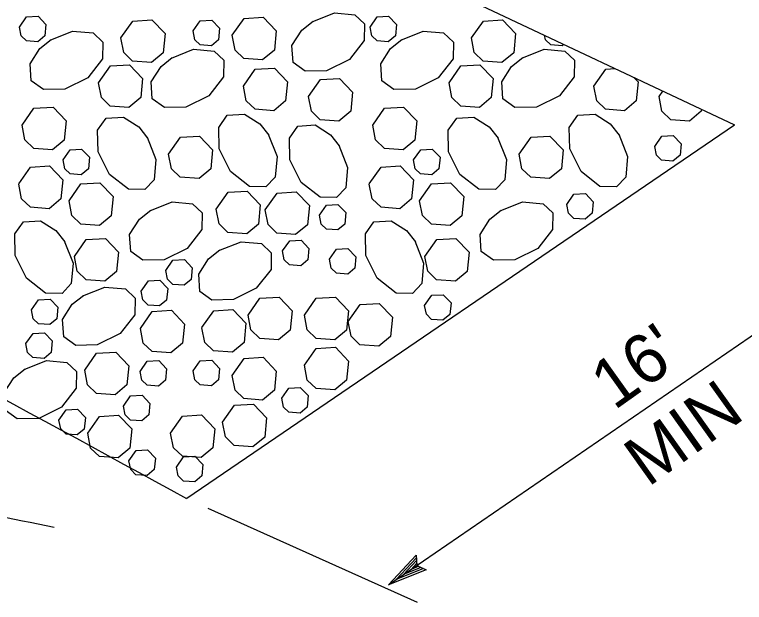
# Model space of a CAD drawing. Extents: x 6709491 to 6710959, y 1869789 to 1870763.
# Drawn here: x 6710751.9 to 6710858.5, y 1870263.6 to 1870349.5 of the extents above; entities that cross this region are included whole.
import ezdxf

# ---------------------------------------------------------------- set-up
doc = ezdxf.new("R2010")
doc.units = 0
for name, color, linetype in [('56 Stg 3 Anno', 7, 'Continuous'), ('57 Undefined', 7, 'Continuous'), ('60 Nongeo Data', 7, 'Continuous')]:
    doc.layers.add(name, color=color, linetype=linetype)

msp = doc.modelspace()

# ---------------------------------------------------------------- linework, layer by layer
at = {"layer": '56 Stg 3 Anno'}
for p, q in [((6710806.49, 1870266.16), (6710885.13, 1870320.15)), ((6710810.73, 1870263.58), (6710780.13, 1870277.31)), ((6710806.49, 1870266.16), (6710810.52, 1870270.48)), ((6710807.59, 1870266.92), (6710810.53, 1870270.06)), ((6710808.68, 1870267.66), (6710810.58, 1870269.69)), ((6710810.52, 1870270.48), (6710810.52, 1870270.48)), ((6710810.52, 1870270.48), (6710810.61, 1870268.99)), ((6710811.22, 1870268.68), (6710808.68, 1870267.66)), ((6710809.77, 1870268.41), (6710810.59, 1870269.28)), ((6710810.9, 1870268.86), (6710809.77, 1870268.41)), ((6710810.61, 1870268.99), (6710811.97, 1870268.36)), ((6710811.97, 1870268.36), (6710806.49, 1870266.16)), ((6710811.6, 1870268.53), (6710807.59, 1870266.91)), ((6710811.97, 1870268.36), (6710811.97, 1870268.36)), ((6710806.49, 1870266.16), (6710806.49, 1870266.16))]:
    msp.add_line(p, q, dxfattribs=at)
at = {"layer": '60 Nongeo Data'}
for p, q in [((6710717.37, 1870399.17), (6710856.99, 1870333.37)), ((6710777.01, 1870278.8), (6710857.03, 1870333.34))]:
    msp.add_line(p, q, dxfattribs=at)
for points in [[(6710795.32, 1870348.4), (6710798.58, 1870349.69), (6710801.57, 1870349.44), (6710802.99, 1870348.09), (6710802.94, 1870345.66), (6710800.79, 1870342.9), (6710797.45, 1870341.24), (6710794.31, 1870341.18), (6710792.55, 1870342.44), (6710792.38, 1870344.94), (6710793.81, 1870347.18), (6710795.46, 1870348.49)], [(6710752.59, 1870347.64), (6710753.63, 1870349.12), (6710755.3, 1870349.22), (6710756.45, 1870348.02), (6710756.29, 1870346.33), (6710755.26, 1870345.48), (6710753.61, 1870345.6), (6710752.84, 1870346.35), (6710752.59, 1870347.64)], [(6710767.4, 1870346.05), (6710769.14, 1870348.52), (6710771.91, 1870348.68), (6710773.85, 1870346.68), (6710773.57, 1870343.88), (6710771.85, 1870342.45), (6710769.11, 1870342.65), (6710767.82, 1870343.9), (6710767.4, 1870346.05)], [(6710777.95, 1870347.07), (6710779, 1870348.55), (6710780.66, 1870348.65), (6710781.82, 1870347.45), (6710781.65, 1870345.76), (6710780.62, 1870344.91), (6710778.98, 1870345.03), (6710778.2, 1870345.78), (6710777.95, 1870347.07)], [(6710783.65, 1870346.43), (6710785.39, 1870348.9), (6710788.17, 1870349.06), (6710790.1, 1870347.06), (6710789.82, 1870344.25), (6710788.1, 1870342.83), (6710785.36, 1870343.02), (6710784.07, 1870344.28), (6710783.65, 1870346.43)], [(6710803.78, 1870347.64), (6710804.82, 1870349.12), (6710806.49, 1870349.22), (6710807.65, 1870348.02), (6710807.48, 1870346.33), (6710806.45, 1870345.48), (6710804.81, 1870345.6), (6710804.03, 1870346.35), (6710803.78, 1870347.64)], [(6710818.59, 1870346.05), (6710820.33, 1870348.52), (6710823.11, 1870348.68), (6710825.04, 1870346.68), (6710824.76, 1870343.88), (6710823.04, 1870342.45), (6710820.3, 1870342.65), (6710819.01, 1870343.9), (6710818.59, 1870346.05)], [(6710757.09, 1870345.73), (6710760.35, 1870347.02), (6710763.34, 1870346.77), (6710764.76, 1870345.42), (6710764.71, 1870342.99), (6710762.56, 1870340.23), (6710759.22, 1870338.57), (6710756.08, 1870338.51), (6710754.32, 1870339.77), (6710754.15, 1870342.27), (6710755.58, 1870344.51), (6710757.23, 1870345.82)], [(6710808.29, 1870345.73), (6710811.54, 1870347.02), (6710814.53, 1870346.77), (6710815.95, 1870345.42), (6710815.9, 1870342.99), (6710813.75, 1870340.23), (6710810.42, 1870338.57), (6710807.28, 1870338.51), (6710805.51, 1870339.77), (6710805.34, 1870342.27), (6710806.78, 1870344.51), (6710808.42, 1870345.82)], [(6710832.07, 1870345.11), (6710831.82, 1870344.91), (6710830.17, 1870345.03), (6710829.4, 1870345.78), (6710829.27, 1870346.43)], [(6710774.77, 1870343.1), (6710778.02, 1870344.39), (6710781.01, 1870344.13), (6710782.43, 1870342.78), (6710782.39, 1870340.36), (6710780.23, 1870337.6), (6710776.9, 1870335.94), (6710773.76, 1870335.88), (6710771.99, 1870337.14), (6710771.83, 1870339.64), (6710773.26, 1870341.88), (6710774.9, 1870343.19)], [(6710825.96, 1870343.1), (6710829.22, 1870344.39), (6710832.21, 1870344.13), (6710833.63, 1870342.78), (6710833.58, 1870340.36), (6710831.43, 1870337.6), (6710828.09, 1870335.94), (6710824.95, 1870335.88), (6710823.19, 1870337.14), (6710823.02, 1870339.64), (6710824.45, 1870341.88), (6710826.1, 1870343.19)], [(6710764.13, 1870339.5), (6710765.87, 1870341.98), (6710768.64, 1870342.14), (6710770.57, 1870340.14), (6710770.29, 1870337.33), (6710768.58, 1870335.9), (6710765.84, 1870336.1), (6710764.55, 1870337.35), (6710764.13, 1870339.5)], [(6710815.32, 1870339.5), (6710817.06, 1870341.98), (6710819.84, 1870342.14), (6710821.77, 1870340.14), (6710821.49, 1870337.33), (6710819.77, 1870335.9), (6710817.03, 1870336.1), (6710815.74, 1870337.35), (6710815.32, 1870339.5)], [(6710785.29, 1870339.02), (6710787.03, 1870341.49), (6710789.81, 1870341.65), (6710791.74, 1870339.65), (6710791.46, 1870336.85), (6710789.74, 1870335.42), (6710787, 1870335.62), (6710785.71, 1870336.87), (6710785.29, 1870339.02)], [(6710836.48, 1870339.02), (6710838.22, 1870341.49), (6710839.58, 1870341.57)], [(6710794.8, 1870337.5), (6710796.54, 1870339.98), (6710799.31, 1870340.14), (6710801.24, 1870338.14), (6710800.97, 1870335.33), (6710799.25, 1870333.9), (6710796.51, 1870334.1), (6710795.22, 1870335.35), (6710794.8, 1870337.5)], [(6710842.32, 1870340.28), (6710842.93, 1870339.65), (6710842.65, 1870336.85), (6710840.93, 1870335.42), (6710838.19, 1870335.62), (6710836.9, 1870336.87), (6710836.48, 1870339.02)], [(6710845.99, 1870337.5), (6710846.54, 1870338.29)], [(6710852.19, 1870335.63), (6710852.16, 1870335.33), (6710850.44, 1870333.9), (6710847.7, 1870334.1), (6710846.41, 1870335.35), (6710845.99, 1870337.5)], [(6710752.97, 1870333.3), (6710754.71, 1870335.77), (6710757.49, 1870335.93), (6710759.42, 1870333.93), (6710759.14, 1870331.12), (6710757.43, 1870329.7), (6710754.68, 1870329.89), (6710753.39, 1870331.15), (6710752.97, 1870333.3)], [(6710804.17, 1870333.3), (6710805.91, 1870335.77), (6710808.68, 1870335.93), (6710810.61, 1870333.93), (6710810.33, 1870331.12), (6710808.62, 1870329.7), (6710805.88, 1870329.89), (6710804.59, 1870331.15), (6710804.17, 1870333.3)], [(6710788.91, 1870331.97), (6710790.2, 1870328.72), (6710789.94, 1870325.73), (6710788.59, 1870324.31), (6710786.16, 1870324.35), (6710783.41, 1870326.51), (6710781.74, 1870329.84), (6710781.69, 1870332.98), (6710782.94, 1870334.75), (6710785.44, 1870334.92), (6710787.68, 1870333.48), (6710788.99, 1870331.84)], [(6710840.1, 1870331.97), (6710841.39, 1870328.72), (6710841.13, 1870325.73), (6710839.78, 1870324.31), (6710837.36, 1870324.35), (6710834.6, 1870326.51), (6710832.94, 1870329.84), (6710832.88, 1870332.98), (6710834.14, 1870334.75), (6710836.64, 1870334.92), (6710838.87, 1870333.48), (6710840.18, 1870331.84)], [(6710771.23, 1870331.55), (6710772.52, 1870328.3), (6710772.26, 1870325.31), (6710770.91, 1870323.89), (6710768.49, 1870323.93), (6710765.73, 1870326.09), (6710764.07, 1870329.42), (6710764.01, 1870332.56), (6710765.27, 1870334.33), (6710767.77, 1870334.49), (6710770, 1870333.06), (6710771.31, 1870331.42)], [(6710822.42, 1870331.55), (6710823.71, 1870328.3), (6710823.46, 1870325.31), (6710822.11, 1870323.89), (6710819.68, 1870323.93), (6710816.92, 1870326.09), (6710815.26, 1870329.42), (6710815.2, 1870332.56), (6710816.46, 1870334.33), (6710818.96, 1870334.49), (6710821.2, 1870333.06), (6710822.51, 1870331.42)], [(6710799.22, 1870330.39), (6710800.51, 1870327.14), (6710800.25, 1870324.15), (6710798.9, 1870322.73), (6710796.48, 1870322.77), (6710793.72, 1870324.93), (6710792.05, 1870328.26), (6710792, 1870331.4), (6710793.26, 1870333.17), (6710795.76, 1870333.34), (6710797.99, 1870331.9), (6710799.3, 1870330.26)], [(6710774.36, 1870329.09), (6710776.09, 1870331.56), (6710778.87, 1870331.72), (6710780.8, 1870329.72), (6710780.52, 1870326.92), (6710778.81, 1870325.49), (6710776.07, 1870325.69), (6710774.78, 1870326.94), (6710774.36, 1870329.09)], [(6710825.55, 1870329.09), (6710827.29, 1870331.56), (6710830.06, 1870331.72), (6710832, 1870329.72), (6710831.72, 1870326.92), (6710830, 1870325.49), (6710827.26, 1870325.69), (6710825.97, 1870326.94), (6710825.55, 1870329.09)], [(6710845.35, 1870330.21), (6710846.39, 1870331.7), (6710848.06, 1870331.79), (6710849.22, 1870330.59), (6710849.05, 1870328.91), (6710848.02, 1870328.05), (6710846.37, 1870328.17), (6710845.6, 1870328.92), (6710845.35, 1870330.21)], [(6710758.95, 1870328.23), (6710759.99, 1870329.71), (6710761.66, 1870329.81), (6710762.82, 1870328.61), (6710762.65, 1870326.92), (6710761.62, 1870326.07), (6710759.97, 1870326.19), (6710759.2, 1870326.94), (6710758.95, 1870328.23)], [(6710810.14, 1870328.23), (6710811.19, 1870329.71), (6710812.85, 1870329.81), (6710814.01, 1870328.61), (6710813.84, 1870326.92), (6710812.81, 1870326.07), (6710811.17, 1870326.19), (6710810.39, 1870326.94), (6710810.14, 1870328.23)], [(6710752.49, 1870324.71), (6710754.22, 1870327.18), (6710757, 1870327.34), (6710758.93, 1870325.34), (6710758.65, 1870322.53), (6710756.94, 1870321.1), (6710754.19, 1870321.3), (6710752.91, 1870322.55), (6710752.49, 1870324.7)], [(6710803.68, 1870324.71), (6710805.42, 1870327.18), (6710808.2, 1870327.34), (6710810.13, 1870325.34), (6710809.85, 1870322.53), (6710808.13, 1870321.1), (6710805.39, 1870321.3), (6710804.1, 1870322.55), (6710803.68, 1870324.7)], [(6710759.83, 1870322.25), (6710761.57, 1870324.72), (6710764.35, 1870324.88), (6710766.28, 1870322.88), (6710766, 1870320.07), (6710764.29, 1870318.65), (6710761.54, 1870318.85), (6710760.26, 1870320.1), (6710759.84, 1870322.25)], [(6710811.03, 1870322.25), (6710812.77, 1870324.72), (6710815.54, 1870324.88), (6710817.48, 1870322.88), (6710817.2, 1870320.07), (6710815.48, 1870318.65), (6710812.74, 1870318.85), (6710811.45, 1870320.1), (6710811.03, 1870322.25)], [(6710781.32, 1870321.02), (6710783.06, 1870323.5), (6710785.83, 1870323.66), (6710787.76, 1870321.65), (6710787.48, 1870318.85), (6710785.77, 1870317.42), (6710783.03, 1870317.62), (6710781.74, 1870318.87), (6710781.32, 1870321.02)], [(6710788.47, 1870320.92), (6710790.21, 1870323.39), (6710792.99, 1870323.55), (6710794.92, 1870321.55), (6710794.64, 1870318.74), (6710792.92, 1870317.32), (6710790.18, 1870317.52), (6710788.89, 1870318.77), (6710788.47, 1870320.92)], [(6710832.52, 1870321.73), (6710833.56, 1870323.22), (6710835.23, 1870323.31), (6710836.39, 1870322.11), (6710836.22, 1870320.43), (6710835.19, 1870319.57), (6710833.54, 1870319.69), (6710832.77, 1870320.44), (6710832.52, 1870321.73)], [(6710771.61, 1870320.8), (6710774.87, 1870322.09), (6710777.86, 1870321.83), (6710779.28, 1870320.48), (6710779.23, 1870318.05), (6710777.08, 1870315.3), (6710773.74, 1870313.63), (6710770.6, 1870313.57), (6710768.84, 1870314.83), (6710768.67, 1870317.33), (6710770.1, 1870319.57), (6710771.75, 1870320.88)], [(6710822.81, 1870320.8), (6710826.06, 1870322.09), (6710829.05, 1870321.83), (6710830.47, 1870320.48), (6710830.43, 1870318.05), (6710828.27, 1870315.3), (6710824.94, 1870313.63), (6710821.8, 1870313.57), (6710820.03, 1870314.83), (6710819.86, 1870317.33), (6710821.3, 1870319.57), (6710822.94, 1870320.88)], [(6710796.39, 1870320.15), (6710797.43, 1870321.64), (6710799.1, 1870321.73), (6710800.25, 1870320.53), (6710800.09, 1870318.85), (6710799.06, 1870317.99), (6710797.41, 1870318.11), (6710796.64, 1870318.86), (6710796.39, 1870320.15)], [(6710759.13, 1870316.4), (6710760.42, 1870313.14), (6710760.16, 1870310.15), (6710758.81, 1870308.73), (6710756.39, 1870308.78), (6710753.63, 1870310.94), (6710751.96, 1870314.27), (6710751.91, 1870317.41), (6710753.16, 1870319.18), (6710755.67, 1870319.34), (6710757.9, 1870317.91), (6710759.21, 1870316.27)], [(6710810.32, 1870316.4), (6710811.61, 1870313.14), (6710811.36, 1870310.15), (6710810, 1870308.73), (6710807.58, 1870308.78), (6710804.82, 1870310.94), (6710803.16, 1870314.27), (6710803.1, 1870317.41), (6710804.36, 1870319.18), (6710806.86, 1870319.34), (6710809.1, 1870317.91), (6710810.41, 1870316.27)], [(6710760.61, 1870314.11), (6710762.35, 1870316.58), (6710765.13, 1870316.74), (6710767.06, 1870314.74), (6710766.78, 1870311.94), (6710765.06, 1870310.51), (6710762.32, 1870310.71), (6710761.03, 1870311.96), (6710760.61, 1870314.11)], [(6710811.8, 1870314.11), (6710813.54, 1870316.58), (6710816.32, 1870316.74), (6710818.25, 1870314.74), (6710817.97, 1870311.94), (6710816.25, 1870310.51), (6710813.51, 1870310.71), (6710812.22, 1870311.96), (6710811.8, 1870314.11)], [(6710781.71, 1870314.98), (6710784.96, 1870316.27), (6710787.95, 1870316.02), (6710789.37, 1870314.66), (6710789.33, 1870312.24), (6710787.17, 1870309.48), (6710783.84, 1870307.82), (6710780.7, 1870307.76), (6710778.93, 1870309.02), (6710778.76, 1870311.52), (6710780.2, 1870313.76), (6710781.84, 1870315.07)], [(6710791, 1870314.93), (6710792.05, 1870316.42), (6710793.71, 1870316.51), (6710794.87, 1870315.31), (6710794.7, 1870313.63), (6710793.67, 1870312.77), (6710792.03, 1870312.89), (6710791.25, 1870313.64), (6710791, 1870314.93)], [(6710797.85, 1870313.71), (6710798.9, 1870315.19), (6710800.56, 1870315.29), (6710801.72, 1870314.09), (6710801.55, 1870312.41), (6710800.53, 1870311.55), (6710798.88, 1870311.67), (6710798.1, 1870312.42), (6710797.85, 1870313.71)], [(6710773.96, 1870312.08), (6710775, 1870313.56), (6710776.67, 1870313.66), (6710777.82, 1870312.46), (6710777.66, 1870310.77), (6710776.63, 1870309.92), (6710774.98, 1870310.04), (6710774.21, 1870310.79), (6710773.96, 1870312.08)], [(6710770.37, 1870309.06), (6710771.41, 1870310.55), (6710773.08, 1870310.64), (6710774.24, 1870309.44), (6710774.07, 1870307.76), (6710773.04, 1870306.9), (6710771.39, 1870307.02), (6710770.62, 1870307.77), (6710770.37, 1870309.06)], [(6710761.82, 1870308.36), (6710765.08, 1870309.65), (6710768.07, 1870309.39), (6710769.49, 1870308.04), (6710769.44, 1870305.61), (6710767.29, 1870302.86), (6710763.96, 1870301.19), (6710760.81, 1870301.13), (6710759.05, 1870302.39), (6710758.88, 1870304.89), (6710760.31, 1870307.13), (6710761.96, 1870308.44)], [(6710785.97, 1870305.54), (6710787.71, 1870308.01), (6710790.49, 1870308.17), (6710792.42, 1870306.17), (6710792.14, 1870303.37), (6710790.42, 1870301.94), (6710787.68, 1870302.14), (6710786.39, 1870303.39), (6710785.97, 1870305.54)], [(6710794.2, 1870305.54), (6710795.94, 1870308.01), (6710798.72, 1870308.17), (6710800.65, 1870306.17), (6710800.37, 1870303.37), (6710798.65, 1870301.94), (6710795.91, 1870302.14), (6710794.62, 1870303.39), (6710794.2, 1870305.54)], [(6710811.75, 1870306.96), (6710812.8, 1870308.45), (6710814.46, 1870308.54), (6710815.62, 1870307.34), (6710815.45, 1870305.66), (6710814.43, 1870304.8), (6710812.78, 1870304.92), (6710812.01, 1870305.67), (6710811.76, 1870306.96)], [(6710754.34, 1870306.33), (6710755.39, 1870307.81), (6710757.05, 1870307.9), (6710758.21, 1870306.7), (6710758.04, 1870305.02), (6710757.02, 1870304.16), (6710755.37, 1870304.28), (6710754.6, 1870305.03), (6710754.34, 1870306.32)], [(6710800.6, 1870304.62), (6710802.34, 1870307.1), (6710805.12, 1870307.26), (6710807.05, 1870305.26), (6710806.77, 1870302.45), (6710805.05, 1870301.02), (6710802.31, 1870301.22), (6710801.02, 1870302.47), (6710800.6, 1870304.62)], [(6710770.25, 1870303.62), (6710771.99, 1870306.1), (6710774.77, 1870306.26), (6710776.7, 1870304.25), (6710776.42, 1870301.45), (6710774.7, 1870300.02), (6710771.96, 1870300.22), (6710770.67, 1870301.47), (6710770.25, 1870303.62)], [(6710779.22, 1870303.73), (6710780.96, 1870306.2), (6710783.74, 1870306.36), (6710785.67, 1870304.36), (6710785.39, 1870301.55), (6710783.68, 1870300.12), (6710780.94, 1870300.32), (6710779.65, 1870301.57), (6710779.23, 1870303.72)], [(6710753.52, 1870301.4), (6710754.57, 1870302.89), (6710756.23, 1870302.98), (6710757.39, 1870301.78), (6710757.22, 1870300.1), (6710756.2, 1870299.24), (6710754.55, 1870299.36), (6710753.78, 1870300.11), (6710753.52, 1870301.4)], [(6710794.2, 1870298.22), (6710795.94, 1870300.69), (6710798.72, 1870300.85), (6710800.65, 1870298.85), (6710800.37, 1870296.05), (6710798.65, 1870294.62), (6710795.91, 1870294.82), (6710794.62, 1870296.07), (6710794.2, 1870298.22)], [(6710762.12, 1870297.52), (6710763.86, 1870300), (6710766.64, 1870300.16), (6710768.57, 1870298.15), (6710768.29, 1870295.35), (6710766.58, 1870293.92), (6710763.83, 1870294.12), (6710762.54, 1870295.37), (6710762.13, 1870297.52)], [(6710753.27, 1870297.62), (6710756.53, 1870298.91), (6710759.51, 1870298.65), (6710760.94, 1870297.3), (6710760.89, 1870294.88), (6710758.73, 1870292.12), (6710755.4, 1870290.46), (6710752.26, 1870290.4), (6710750.49, 1870291.66), (6710750.33, 1870294.16), (6710751.76, 1870296.4), (6710753.4, 1870297.71)], [(6710770.21, 1870297.34), (6710771.26, 1870298.83), (6710772.92, 1870298.92), (6710774.08, 1870297.72), (6710773.91, 1870296.04), (6710772.88, 1870295.18), (6710771.24, 1870295.3), (6710770.46, 1870296.05), (6710770.21, 1870297.34)], [(6710777.95, 1870297.4), (6710779, 1870298.88), (6710780.66, 1870298.98), (6710781.82, 1870297.77), (6710781.65, 1870296.09), (6710780.62, 1870295.24), (6710778.98, 1870295.36), (6710778.2, 1870296.11), (6710777.95, 1870297.4)], [(6710783.65, 1870296.75), (6710785.39, 1870299.23), (6710788.17, 1870299.39), (6710790.1, 1870297.39), (6710789.82, 1870294.58), (6710788.1, 1870293.15), (6710785.36, 1870293.35), (6710784.07, 1870294.6), (6710783.65, 1870296.75)], [(6710790.89, 1870293.41), (6710791.94, 1870294.89), (6710793.6, 1870294.99), (6710794.76, 1870293.79), (6710794.6, 1870292.11), (6710793.57, 1870291.25), (6710791.92, 1870291.37), (6710791.15, 1870292.12), (6710790.9, 1870293.41)], [(6710767.78, 1870292.27), (6710768.82, 1870293.76), (6710770.49, 1870293.85), (6710771.65, 1870292.65), (6710771.48, 1870290.97), (6710770.45, 1870290.11), (6710768.8, 1870290.23), (6710768.03, 1870290.98), (6710767.78, 1870292.27)], [(6710782.24, 1870289.91), (6710783.98, 1870292.38), (6710786.75, 1870292.54), (6710788.68, 1870290.54), (6710788.41, 1870287.74), (6710786.69, 1870286.31), (6710783.95, 1870286.51), (6710782.66, 1870287.76), (6710782.24, 1870289.91)], [(6710758.36, 1870290.22), (6710759.4, 1870291.7), (6710761.07, 1870291.8), (6710762.23, 1870290.59), (6710762.06, 1870288.91), (6710761.03, 1870288.06), (6710759.39, 1870288.18), (6710758.61, 1870288.93), (6710758.36, 1870290.22)], [(6710762.55, 1870288.29), (6710764.29, 1870290.76), (6710767.06, 1870290.92), (6710768.99, 1870288.92), (6710768.71, 1870286.11), (6710767, 1870284.69), (6710764.26, 1870284.88), (6710762.97, 1870286.14), (6710762.55, 1870288.29)], [(6710774.67, 1870288.33), (6710776.41, 1870290.81), (6710779.18, 1870290.97), (6710781.12, 1870288.96), (6710780.84, 1870286.16), (6710779.12, 1870284.73), (6710776.38, 1870284.93), (6710775.09, 1870286.18), (6710774.67, 1870288.33)], [(6710768.58, 1870284.29), (6710769.62, 1870285.77), (6710771.29, 1870285.87), (6710772.44, 1870284.66), (6710772.28, 1870282.98), (6710771.25, 1870282.13), (6710769.6, 1870282.24), (6710768.83, 1870283), (6710768.58, 1870284.29)], [(6710775.51, 1870283.36), (6710776.55, 1870284.85), (6710778.22, 1870284.94), (6710779.38, 1870283.74), (6710779.21, 1870282.06), (6710778.18, 1870281.2), (6710776.53, 1870281.32), (6710775.76, 1870282.07), (6710775.51, 1870283.36)]]:
    msp.add_lwpolyline(points, dxfattribs=at)
for points in [[(6710505.99, 1870337.51), (6710532.99, 1870347.83), (6710590.83, 1870352.57), (6710625.79, 1870346.13), (6710776.97, 1870278.77)], [(6710757.64, 1870274.53), (6710720.56, 1870280.95), (6710700.05, 1870282.48)]]:
    msp.add_spline(points, degree=3, dxfattribs=at)

# ---------------------------------------------------------------- texts
at = {"layer": '57 Undefined'}
for s, p in [("16'", (6710839.44, 1870291.56)), ('MIN', (6710844.37, 1870280.35))]:
    msp.add_text(s, height=7.2, rotation=35.4657, dxfattribs=at).set_placement(p)

doc.saveas('drawing.dxf')
